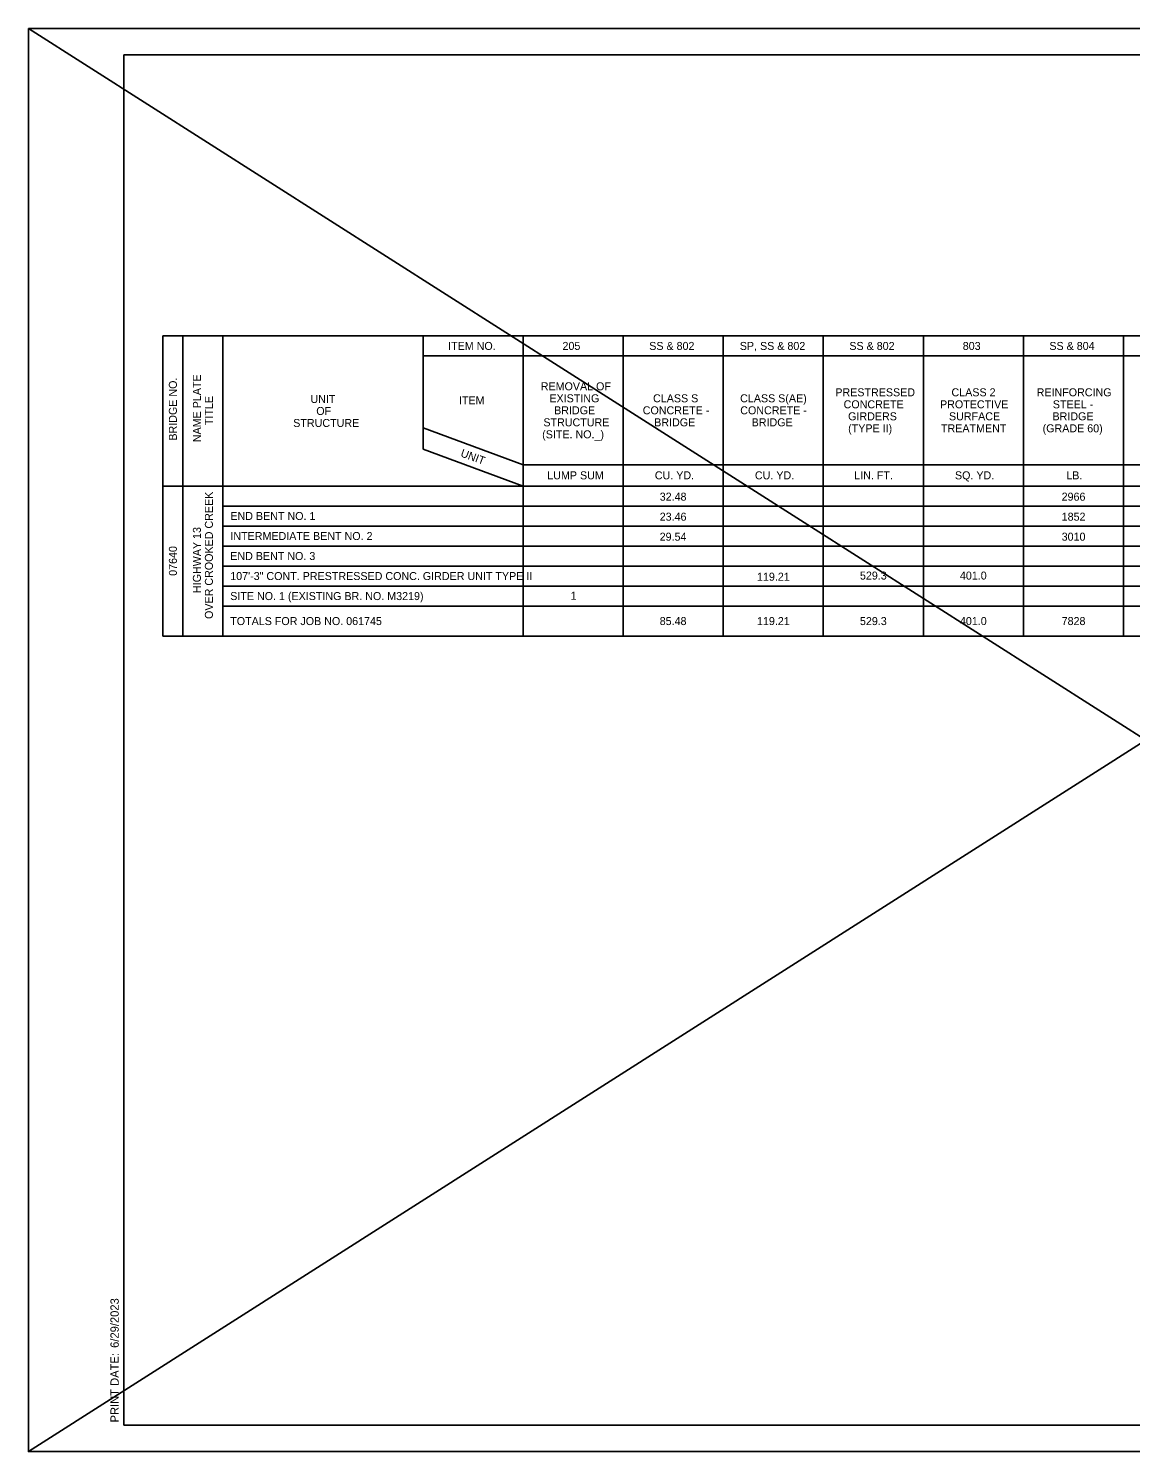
# Model space of a CAD drawing. Extents: x 1390434.7 to 1390467.9, y 1966884.5 to 1966897.9.
# Drawn here: x 1390434.69 to 1390440.2, y 1966890.78 to 1966897.89 of the extents above; entities that cross this region are included whole.
import ezdxf

# ---------------------------------------------------------------- set-up
doc = ezdxf.new("R2010")
doc.units = 0
for name, color, linetype in [('B_Border', 7, 'Continuous'), ('B_No_Plot', 7, 'Continuous'), ('Default', 7, 'Continuous')]:
    doc.layers.add(name, color=color, linetype=linetype)

msp = doc.modelspace()

# ---------------------------------------------------------------- linework, layer by layer
at = {"layer": 'B_Border'}
for p, q in [((1390435.1658, 1966897.7561), (1390445.7041, 1966897.7561)), ((1390435.1658, 1966890.9078), (1390435.1658, 1966897.7561)), ((1390445.7041, 1966890.9078), (1390435.1658, 1966890.9078))]:
    msp.add_line(p, q, dxfattribs=at)
at = {"layer": 'B_No_Plot'}
msp.add_lwpolyline([(1390434.6899, 1966897.8879), (1390445.8566, 1966897.8879), (1390445.8566, 1966890.7759), (1390434.6899, 1966890.7759)], close=True, dxfattribs=at)
at = {"layer": 'Default'}
for p, q in [((1390434.6899, 1966897.8879), (1390445.8566, 1966890.7759)), ((1390445.8566, 1966897.8879), (1390434.6899, 1966890.7759)), ((1390435.3616, 1966896.3513), (1390435.3616, 1966895.6013)), ((1390435.3616, 1966896.3513), (1390435.4616, 1966896.3513)), ((1390435.4616, 1966896.3513), (1390435.6616, 1966896.3513)), ((1390435.4616, 1966896.3513), (1390435.4616, 1966895.6013)), ((1390435.6616, 1966896.3513), (1390435.6616, 1966895.6013)), ((1390435.6616, 1966896.3513), (1390436.6616, 1966896.3513)), ((1390436.6616, 1966896.3513), (1390437.1616, 1966896.3513)), ((1390436.6616, 1966896.3513), (1390436.6616, 1966895.8926)), ((1390437.1616, 1966896.3513), (1390437.6616, 1966896.3513)), ((1390437.1616, 1966896.3513), (1390437.1616, 1966896.2513)), ((1390437.6616, 1966896.3513), (1390437.6616, 1966894.8513)), ((1390437.6616, 1966896.3513), (1390438.1616, 1966896.3513)), ((1390438.1616, 1966896.3513), (1390438.1616, 1966894.8513)), ((1390438.1616, 1966896.3513), (1390438.6616, 1966896.3513)), ((1390438.6616, 1966896.3513), (1390438.6616, 1966894.8513)), ((1390438.6616, 1966896.3513), (1390439.1616, 1966896.3513)), ((1390439.1616, 1966896.3513), (1390439.1616, 1966894.8513)), ((1390439.1616, 1966896.3513), (1390439.6616, 1966896.3513)), ((1390439.6616, 1966896.3513), (1390439.6616, 1966894.8513)), ((1390439.6616, 1966896.3513), (1390440.1616, 1966896.3513)), ((1390440.1616, 1966896.3513), (1390440.1616, 1966894.8513)), ((1390440.1616, 1966896.3513), (1390440.6616, 1966896.3513)), ((1390436.6616, 1966896.2513), (1390444.1616, 1966896.2513)), ((1390437.1616, 1966896.2513), (1390437.1616, 1966895.7079)), ((1390436.6616, 1966895.8926), (1390436.6616, 1966895.786)), ((1390436.6616, 1966895.8926), (1390437.1616, 1966895.7079)), ((1390436.6616, 1966895.786), (1390437.1616, 1966895.6013)), ((1390437.1616, 1966895.7079), (1390437.1616, 1966895.6013)), ((1390437.1616, 1966895.7079), (1390437.6616, 1966895.7079)), ((1390437.6616, 1966895.7079), (1390438.1616, 1966895.7079)), ((1390438.1616, 1966895.7079), (1390438.6616, 1966895.7079)), ((1390438.6616, 1966895.7079), (1390439.1616, 1966895.7079)), ((1390439.1616, 1966895.7079), (1390439.6616, 1966895.7079)), ((1390439.6616, 1966895.7079), (1390440.1616, 1966895.7079)), ((1390440.1616, 1966895.7079), (1390440.6616, 1966895.7079)), ((1390435.3616, 1966895.6013), (1390435.3616, 1966894.8513)), ((1390435.6616, 1966895.6013), (1390435.3616, 1966895.6013)), ((1390435.4616, 1966895.6013), (1390435.4616, 1966894.8513)), ((1390435.6616, 1966895.6013), (1390437.1616, 1966895.6013)), ((1390435.6616, 1966895.6013), (1390435.6616, 1966895.5013)), ((1390437.1616, 1966895.6013), (1390437.1616, 1966894.8513)), ((1390437.1616, 1966895.6013), (1390437.6616, 1966895.6013)), ((1390437.6616, 1966895.6013), (1390438.1616, 1966895.6013)), ((1390438.1616, 1966895.6013), (1390438.6616, 1966895.6013)), ((1390438.6616, 1966895.6013), (1390439.1616, 1966895.6013)), ((1390439.1616, 1966895.6013), (1390439.6616, 1966895.6013)), ((1390439.6616, 1966895.6013), (1390440.1616, 1966895.6013)), ((1390440.1616, 1966895.6013), (1390440.6616, 1966895.6013)), ((1390435.6616, 1966895.5013), (1390444.1616, 1966895.5013)), ((1390435.6616, 1966895.5013), (1390435.6616, 1966895.4013)), ((1390435.6616, 1966895.4013), (1390444.1616, 1966895.4013)), ((1390435.6616, 1966895.4013), (1390435.6616, 1966895.3013)), ((1390435.6616, 1966895.3013), (1390444.1616, 1966895.3013)), ((1390435.6616, 1966895.3013), (1390435.6616, 1966895.2013)), ((1390435.6616, 1966895.2013), (1390444.1616, 1966895.2013)), ((1390435.6616, 1966895.2013), (1390435.6616, 1966895.1013)), ((1390435.6616, 1966895.1013), (1390444.1616, 1966895.1013)), ((1390435.6616, 1966895.1013), (1390435.6616, 1966895.0013)), ((1390435.6616, 1966895.0013), (1390435.6616, 1966894.8513)), ((1390435.6616, 1966895.0013), (1390444.1616, 1966895.0013)), ((1390435.3616, 1966894.8513), (1390435.6616, 1966894.8513)), ((1390435.6616, 1966894.8513), (1390444.1616, 1966894.8513))]:
    msp.add_line(p, q, dxfattribs=at)

# ---------------------------------------------------------------- texts
at = {"layer": 'B_Border'}
for s, p in [('ITEM NO.', (1390436.7869, 1966896.2813)), ('205', (1390437.3584, 1966896.2813)), ('SS & 802', (1390437.7918, 1966896.2813)), ('SP, SS & 802', (1390438.2444, 1966896.2813)), ('SS & 802', (1390438.7918, 1966896.2813)), ('803', (1390439.3585, 1966896.2813)), ('SS & 804', (1390439.7913, 1966896.2813)), ('CU. YD.', (1390437.8199, 1966895.6346)), ('LIN. FT.', (1390438.8162, 1966895.6346)), ('SQ. YD.', (1390439.3196, 1966895.6346)), ('LB.', (1390439.876, 1966895.6346)), ('32.48', (1390437.8442, 1966895.528)), ('2966', (1390439.8525, 1966895.528)), ('23.46', (1390437.8441, 1966895.428)), ('1852', (1390439.8528, 1966895.428)), ('29.54', (1390437.8439, 1966895.328)), ('3010', (1390439.8527, 1966895.328)), ('107\'-3" CONT. PRESTRESSED CONC. GIRDER UNIT TYPE II', (1390435.6981, 1966895.1313)), ('529.3', (1390438.8448, 1966895.1337)), ('401.0', (1390439.3443, 1966895.1337)), ('119.21', (1390438.3304, 1966895.128)), ('1', (1390437.3988, 1966895.0328)), ('85.48', (1390437.8442, 1966894.9063)), ('119.21', (1390438.3304, 1966894.9063)), ('7828', (1390439.8526, 1966894.9063))]:
    msp.add_text(s, height=0.04, dxfattribs=at).set_placement(p)
for s, height, rotation, p in [('BRIDGE NO.', 0.04, 90, (1390435.4316, 1966895.8281)), ('NAME PLATE', 0.04, 90, (1390435.5516, 1966895.8203)), ('REMOVAL OF', 0.04, 360, (1390437.2498, 1966896.0796)), ('TITLE', 0.04, 90, (1390435.6116, 1966895.9057)), ('UNIT', 0.04, 360, (1390436.0989, 1966896.0163)), ('ITEM', 0.04, 360, (1390436.8411, 1966896.0096)), ('EXISTING', 0.04, 360, (1390437.2929, 1966896.0196)), ('CLASS S', 0.04, 360, (1390437.811, 1966896.0196)), ('CLASS S(AE)', 0.04, 360, (1390438.246, 1966896.0196)), ('PRESTRESSED', 0.04, 360, (1390438.7217, 1966896.0496)), ('CONCRETE ', 0.04, 360, (1390438.7631, 1966895.9896)), ('PROTECTIVE ', 0.04, 360, (1390439.2449, 1966895.9896)), ('CLASS 2', 0.04, 360, (1390439.3022, 1966896.0496)), ('REINFORCING', 0.04, 360, (1390439.7277, 1966896.0496)), ('STEEL -', 0.04, 360, (1390439.8086, 1966895.9896)), ('OF ', 0.04, 360, (1390436.1281, 1966895.9563)), ('BRIDGE', 0.04, 360, (1390437.3165, 1966895.9596)), ('CONCRETE -', 0.04, 360, (1390437.7594, 1966895.9596)), ('CONCRETE -', 0.04, 360, (1390438.2466, 1966895.9596)), ('GIRDERS', 0.04, 360, (1390438.7856, 1966895.9296)), ('SURFACE ', 0.04, 360, (1390439.2896, 1966895.9296)), ('BRIDGE', 0.04, 360, (1390439.8068, 1966895.9296)), ('STRUCTURE', 0.04, 360, (1390436.0129, 1966895.8963)), ('(SITE. NO._)', 0.04, 360, (1390437.2568, 1966895.8396)), ('STRUCTURE', 0.04, 360, (1390437.2629, 1966895.8996)), ('BRIDGE', 0.04, 360, (1390437.8165, 1966895.8996)), ('BRIDGE', 0.04, 360, (1390438.3037, 1966895.8996)), ('(TYPE II)', 0.04, 360, (1390438.7858, 1966895.8696)), ('TREATMENT', 0.04, 360, (1390439.2497, 1966895.8696)), ('(GRADE 60)', 0.04, 360, (1390439.7576, 1966895.8696)), ('UNIT', 0.04, 339.7243, (1390436.8458, 1966895.7499)), ('LUMP SUM', 0.04, 360, (1390437.2824, 1966895.6346)), ('CU. YD.', 0.04, 360, (1390438.3199, 1966895.6346)), ('OVER CROOKED CREEK', 0.04, 90, (1390435.6116, 1966894.9369)), ('END BENT NO. 1', 0.04, 360, (1390435.6988, 1966895.4313)), ('HIGHWAY 13 ', 0.04, 90, (1390435.5516, 1966895.0663)), ('INTERMEDIATE BENT NO. 2', 0.04, 360, (1390435.6988, 1966895.3313)), ('07640', 0.04, 90, (1390435.4316, 1966895.1523)), ('END BENT NO. 3', 0.04, 360, (1390435.6981, 1966895.2313)), ('SITE NO. 1 (EXISTING BR. NO. M3219)', 0.04, 360, (1390435.6981, 1966895.0313)), ('TOTALS FOR JOB NO. 061745', 0.04, 360, (1390435.6981, 1966894.9063)), ('529.3', 0.04, 360, (1390438.8448, 1966894.9063)), ('401.0', 0.04, 360, (1390439.3443, 1966894.9063)), ('6/29/2023', 0.04167, 90, (1390435.1411, 1966891.2941)), ('PRINT DATE:  ', 0.041667, 90, (1390435.1411, 1966890.9214))]:
    msp.add_text(s, height=height, rotation=rotation, dxfattribs=at).set_placement(p)

doc.saveas('drawing.dxf')
